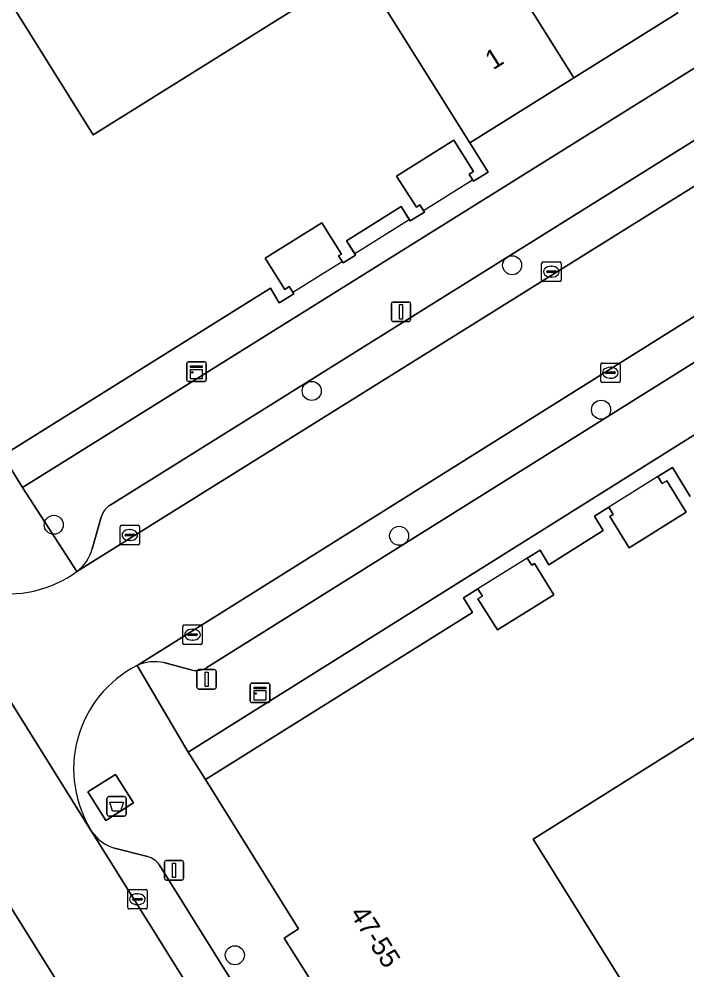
# Model space of a CAD drawing. Extents: x 159664 to 160323, y 385312 to 386115.
# Drawn here: x 159990.16 to 160024.46, y 385782.67 to 385831.48 of the extents above; entities that cross this region are included whole.
import ezdxf

# ---------------------------------------------------------------- set-up
doc = ezdxf.new("R2010")
doc.units = 0
for name, color, linetype in [('IMGEO_Afval_apart_plaats', 7, 'Continuous'), ('IMGEO_Boom', 7, 'Continuous'), ('IMGEO_Erf', 7, 'Continuous'), ('IMGEO_Kast', 7, 'Continuous'), ('IMGEO_Kolk', 7, 'Continuous'), ('IMGEO_Lichtmast', 7, 'Continuous'), ('IMGEO_Pand', 7, 'Continuous'), ('IMGEO_Pand_nummerreeks', 7, 'Continuous'), ('IMGEO_Pand_overbouw', 7, 'Continuous'), ('IMGEO_Parkeervlak_open', 7, 'Continuous'), ('IMGEO_Rijbaan_lokaal_open', 7, 'Continuous'), ('IMGEO_Voetpad_gesloten', 7, 'Continuous'), ('IMGEO_Voetpad_open', 7, 'Continuous')]:
    doc.layers.add(name, color=color, linetype=linetype)

msp = doc.modelspace()

# ---------------------------------------------------------------- linework, layer by layer
at = {"layer": 'IMGEO_Afval_apart_plaats'}
for p, q in [((159994.675, 385790.674), (159994.675, 385791.474)), ((159994.675, 385791.474), (159994.675, 385790.674)), ((159994.775, 385791.574), (159995.565, 385791.574)), ((159995.565, 385791.574), (159994.775, 385791.574)), ((159995.665, 385791.474), (159995.665, 385790.674)), ((159995.665, 385790.674), (159995.665, 385791.474)), ((159995.565, 385790.574), (159994.775, 385790.574)), ((159994.775, 385790.574), (159995.565, 385790.574))]:
    msp.add_line(p, q, dxfattribs=at)
msp.add_lwpolyline([(159994.818, 385791.288), (159995.522, 385791.288), (159995.373, 385790.818), (159994.967, 385790.818), (159994.818, 385791.288)], dxfattribs=at)
for centre, start, end in [((159994.775, 385791.474), 90, 180), ((159994.775, 385791.474), 90, 180), ((159995.565, 385791.474), 0, 90), ((159995.565, 385791.474), 360, 90), ((159994.775, 385790.674), 180, 270), ((159994.775, 385790.674), 180, 270), ((159995.565, 385790.674), 270, 0), ((159995.565, 385790.674), 270, 0)]:
    msp.add_arc(centre, 0.1, start, end, dxfattribs=at)
at = {"layer": 'IMGEO_Boom'}
for centre in [(160015.483, 385818.84), (160005.192, 385812.388), (160020.052, 385811.427), (159991.944, 385805.52), (160009.679, 385804.956), (160001.243, 385783.428)]:
    msp.add_circle(centre, 0.489, dxfattribs=at)
at = {"layer": 'IMGEO_Erf'}
for points in [[(159986.779, 385837.03), (159993.962, 385825.534), (160007.687, 385834.102)], [(160023.99, 385831.793), (160018.647, 385828.455), (160013.305, 385825.116), (160014.244, 385823.616), (160013.502, 385823.151), (160013.274, 385823.516), (160013.494, 385823.654), (160012.491, 385825.256), (160009.552, 385823.409), (160010.574, 385821.819), (160010.751, 385821.933), (160010.983, 385821.572), (160010.245, 385821.112), (160009.785, 385821.85), (160006.978, 385820.1), (160007.447, 385819.366), (160006.799, 385818.956), (160006.571, 385819.321), (160006.715, 385819.411), (160005.715, 385821.015), (160002.808, 385819.202), (160003.803, 385817.596), (160004.041, 385817.743), (160004.267, 385817.378), (160003.524, 385816.917), (160003.066, 385817.656), (159989.327, 385809.076), (159990.336, 385807.428), (160038.523, 385837.501)], [(160047.785, 385824.505), (159998.838, 385793.855), (159999.73, 385792.444), (160013.448, 385801.025), (160012.988, 385801.763), (160013.729, 385802.225), (160013.956, 385801.861), (160013.727, 385801.718), (160014.723, 385800.123), (160017.631, 385801.928), (160016.64, 385803.538), (160016.487, 385803.443), (160016.261, 385803.81), (160016.917, 385804.213), (160017.373, 385803.472), (160020.164, 385805.223), (160019.705, 385805.962), (160020.443, 385806.42), (160020.669, 385806.054), (160020.498, 385805.949), (160021.488, 385804.339), (160024.423, 385806.167), (160023.434, 385807.777), (160023.195, 385807.631), (160022.97, 385807.997), (160023.715, 385808.455), (160024.631, 385806.964)], [(160045.382, 385808.721), (160040.222, 385805.5), (160041.856, 385802.883), (160036.512, 385799.546), (160034.877, 385802.164), (160029.715, 385798.943), (160029.532, 385798.829), (160030.123, 385797.883), (160016.558, 385789.392), (160023.715, 385777.928)]]:
    msp.add_lwpolyline(points, dxfattribs=at)
at = {"layer": 'IMGEO_Kast'}
for p, q in [((159998.777, 385812.955), (159998.777, 385813.796)), ((159998.777, 385813.796), (159998.777, 385812.955)), ((159998.852, 385813.88), (159999.693, 385813.88)), ((159999.693, 385813.88), (159998.852, 385813.88)), ((159999.777, 385813.805), (159999.777, 385812.964)), ((159999.777, 385812.964), (159999.777, 385813.805)), ((159999.702, 385812.88), (159998.861, 385812.88)), ((159998.861, 385812.88), (159999.702, 385812.88)), ((160002.037, 385796.472), (160002.037, 385797.313)), ((160002.037, 385797.313), (160002.037, 385796.472)), ((160002.112, 385797.397), (160002.953, 385797.397)), ((160002.953, 385797.397), (160002.112, 385797.397)), ((160003.037, 385797.322), (160003.037, 385796.481)), ((160003.037, 385796.481), (160003.037, 385797.322)), ((160002.962, 385796.397), (160002.121, 385796.397)), ((160002.121, 385796.397), (160002.962, 385796.397))]:
    msp.add_line(p, q, dxfattribs=at)
for points in [[(159998.972, 385813.67), (159999.572, 385813.67), (159999.572, 385813.585), (159998.972, 385813.585), (159998.972, 385813.67)], [(159998.972, 385813.495), (159999.572, 385813.495), (159999.572, 385813.006), (159998.972, 385813.006), (159998.972, 385813.495)], [(160002.232, 385797.187), (160002.832, 385797.187), (160002.832, 385797.102), (160002.232, 385797.102), (160002.232, 385797.187)], [(160002.232, 385797.012), (160002.832, 385797.012), (160002.832, 385796.523), (160002.232, 385796.523), (160002.232, 385797.012)]]:
    msp.add_lwpolyline(points, dxfattribs=at)
for centre in [(159999.056, 385813.344), (160002.316, 385796.861)]:
    msp.add_circle(centre, 0.0377, dxfattribs=at)
for centre, start, end in [((159998.855, 385813.802), 92.4484, 184.2845), ((159998.855, 385813.802), 92.4484, 184.2845), ((159999.699, 385813.802), 2.4484, 94.2845), ((159999.699, 385813.802), 2.4484, 94.2845), ((159998.855, 385812.958), 182.4484, 274.2845), ((159998.855, 385812.958), 182.4484, 274.2845), ((159999.699, 385812.958), 272.4484, 4.2845), ((159999.699, 385812.958), 272.4484, 4.2845), ((160002.115, 385797.319), 92.4484, 184.2845), ((160002.115, 385797.319), 92.4484, 184.2845), ((160002.959, 385797.319), 2.4484, 94.2845), ((160002.959, 385797.319), 2.4484, 94.2845), ((160002.115, 385796.475), 182.4484, 274.2845), ((160002.115, 385796.475), 182.4484, 274.2845), ((160002.959, 385796.475), 272.4484, 4.2845), ((160002.959, 385796.475), 272.4484, 4.2845)]:
    msp.add_arc(centre, 0.0779, start, end, dxfattribs=at)
at = {"layer": 'IMGEO_Kolk'}
for p, q in [((160017.073, 385819.009), (160017.925, 385819.009)), ((160016.998, 385818.083), (160016.998, 385818.935)), ((160017.257, 385818.503), (160017.257, 385818.515)), ((160017.3, 385818.552), (160017.698, 385818.552)), ((160017.486, 385818.789), (160017.511, 385818.789)), ((160017.741, 385818.515), (160017.741, 385818.503)), ((160017.999, 385818.935), (160017.999, 385818.083)), ((160017.925, 385818.009), (160017.073, 385818.009)), ((160017.695, 385818.466), (160017.297, 385818.466)), ((160017.509, 385818.229), (160017.484, 385818.229)), ((160020.03, 385812.897), (160020.03, 385813.749)), ((160020.105, 385813.823), (160020.957, 385813.823)), ((160020.518, 385813.603), (160020.543, 385813.603)), ((160021.031, 385813.749), (160021.031, 385812.897)), ((160020.289, 385813.317), (160020.289, 385813.329)), ((160020.727, 385813.28), (160020.329, 385813.28)), ((160020.332, 385813.366), (160020.73, 385813.366)), ((160020.773, 385813.329), (160020.773, 385813.317)), ((160020.957, 385812.823), (160020.105, 385812.823)), ((160020.541, 385813.043), (160020.516, 385813.043)), ((159995.35, 385804.567), (159995.35, 385805.419)), ((159995.425, 385805.493), (159996.277, 385805.493)), ((159996.351, 385805.419), (159996.351, 385804.567)), ((159995.609, 385804.987), (159995.609, 385804.999)), ((159996.047, 385804.95), (159995.649, 385804.95)), ((159995.652, 385805.036), (159996.05, 385805.036)), ((159995.838, 385805.273), (159995.863, 385805.273)), ((159996.093, 385804.999), (159996.093, 385804.987)), ((159996.277, 385804.493), (159995.425, 385804.493)), ((159995.861, 385804.713), (159995.836, 385804.713)), ((159998.57, 385799.452), (159998.57, 385800.304)), ((159998.645, 385800.378), (159999.497, 385800.378)), ((159999.058, 385800.158), (159999.083, 385800.158)), ((159999.571, 385800.304), (159999.571, 385799.452)), ((159998.829, 385799.872), (159998.829, 385799.884)), ((159999.267, 385799.835), (159998.869, 385799.835)), ((159998.872, 385799.921), (159999.27, 385799.921)), ((159999.081, 385799.598), (159999.056, 385799.598)), ((159999.313, 385799.884), (159999.313, 385799.872)), ((159999.497, 385799.378), (159998.645, 385799.378)), ((159995.816, 385786.802), (159996.668, 385786.802)), ((159995.741, 385785.876), (159995.741, 385786.728)), ((159996, 385786.296), (159996, 385786.308)), ((159996.043, 385786.345), (159996.441, 385786.345)), ((159996.229, 385786.582), (159996.254, 385786.582)), ((159996.484, 385786.308), (159996.484, 385786.296)), ((159996.742, 385786.728), (159996.742, 385785.876)), ((159996.668, 385785.802), (159995.816, 385785.802)), ((159996.438, 385786.259), (159996.04, 385786.259)), ((159996.252, 385786.022), (159996.227, 385786.022))]:
    msp.add_line(p, q, dxfattribs=at)
for points in [[(160017.073, 385819.009), (160017.925, 385819.009)], [(160016.998, 385818.083), (160016.998, 385818.935)], [(160017.999, 385818.935), (160017.999, 385818.083)], [(160017.925, 385818.009), (160017.073, 385818.009)], [(160020.03, 385812.897), (160020.03, 385813.749)], [(160020.105, 385813.823), (160020.957, 385813.823)], [(160021.031, 385813.749), (160021.031, 385812.897)], [(160020.957, 385812.823), (160020.105, 385812.823)], [(159995.35, 385804.567), (159995.35, 385805.419)], [(159995.425, 385805.493), (159996.277, 385805.493)], [(159996.351, 385805.419), (159996.351, 385804.567)], [(159996.277, 385804.493), (159995.425, 385804.493)], [(159998.57, 385799.452), (159998.57, 385800.304)], [(159998.645, 385800.378), (159999.497, 385800.378)], [(159999.571, 385800.304), (159999.571, 385799.452)], [(159999.497, 385799.378), (159998.645, 385799.378)], [(159995.816, 385786.802), (159996.668, 385786.802)], [(159995.741, 385785.876), (159995.741, 385786.728)], [(159996.742, 385786.728), (159996.742, 385785.876)], [(159996.668, 385785.802), (159995.816, 385785.802)]]:
    msp.add_lwpolyline(points, dxfattribs=at)
for centre, radius, start, end in [((160017.075, 385818.933), 0.0765, 91.552, 178.448), ((160017.075, 385818.933), 0.0765, 91.552, 178.448), ((160017.923, 385818.933), 0.0765, 1.552, 88.448), ((160017.923, 385818.933), 0.0765, 1.552, 88.448), ((160017.297, 385818.512), 0.0403, 85.8775, 175.7526), ((160017.294, 385818.502), 0.0366, 178.938, 274.7102), ((160017.698, 385818.509), 0.043, 264.8664, 352.4533), ((160017.702, 385818.514), 0.0386, 1.7309, 96.639), ((160017.075, 385818.085), 0.0765, 181.552, 268.448), ((160017.075, 385818.085), 0.0765, 181.552, 268.448), ((160017.923, 385818.085), 0.0765, 271.552, 358.448), ((160017.923, 385818.085), 0.0765, 271.552, 358.448), ((160020.107, 385813.747), 0.0765, 91.552, 178.448), ((160020.107, 385813.747), 0.0765, 91.552, 178.448), ((160020.955, 385813.747), 0.0765, 1.552, 88.448), ((160020.955, 385813.747), 0.0765, 1.552, 88.448), ((160020.329, 385813.326), 0.0403, 85.8775, 175.7526), ((160020.326, 385813.316), 0.0366, 178.938, 274.7102), ((160020.73, 385813.323), 0.043, 264.8664, 352.4533), ((160020.734, 385813.328), 0.0386, 1.7309, 96.639), ((160020.107, 385812.899), 0.0765, 181.552, 268.448), ((160020.107, 385812.899), 0.0765, 181.552, 268.448), ((160020.955, 385812.899), 0.0765, 271.552, 358.448), ((160020.955, 385812.899), 0.0765, 271.552, 358.448), ((159995.427, 385805.417), 0.0765, 91.552, 178.448), ((159995.427, 385805.417), 0.0765, 91.552, 178.448), ((159996.275, 385805.417), 0.0765, 1.552, 88.448), ((159996.275, 385805.417), 0.0765, 1.552, 88.448), ((159995.649, 385804.996), 0.0403, 85.8775, 175.7526), ((159995.646, 385804.986), 0.0366, 178.938, 274.7102), ((159996.05, 385804.993), 0.043, 264.8664, 352.4533), ((159996.054, 385804.998), 0.0386, 1.7309, 96.639), ((159995.427, 385804.569), 0.0765, 181.552, 268.448), ((159995.427, 385804.569), 0.0765, 181.552, 268.448), ((159996.275, 385804.569), 0.0765, 271.552, 358.448), ((159996.275, 385804.569), 0.0765, 271.552, 358.448), ((159998.647, 385800.302), 0.0765, 91.552, 178.448), ((159998.647, 385800.302), 0.0765, 91.552, 178.448), ((159999.495, 385800.302), 0.0765, 1.552, 88.448), ((159999.495, 385800.302), 0.0765, 1.552, 88.448), ((159998.647, 385799.454), 0.0765, 181.552, 268.448), ((159998.647, 385799.454), 0.0765, 181.552, 268.448), ((159998.869, 385799.881), 0.0403, 85.8775, 175.7526), ((159998.866, 385799.871), 0.0366, 178.938, 274.7102), ((159999.27, 385799.878), 0.043, 264.8664, 352.4533), ((159999.274, 385799.883), 0.0386, 1.7309, 96.639), ((159999.495, 385799.454), 0.0765, 271.552, 358.448), ((159999.495, 385799.454), 0.0765, 271.552, 358.448), ((159995.818, 385786.726), 0.0765, 91.552, 178.448), ((159995.818, 385786.726), 0.0765, 91.552, 178.448), ((159996.666, 385786.726), 0.0765, 1.552, 88.448), ((159996.666, 385786.726), 0.0765, 1.552, 88.448), ((159996.04, 385786.305), 0.0403, 85.8775, 175.7526), ((159996.037, 385786.295), 0.0366, 178.938, 274.7102), ((159996.441, 385786.302), 0.043, 264.8664, 352.4533), ((159996.445, 385786.307), 0.0386, 1.7309, 96.639), ((159995.818, 385785.878), 0.0765, 181.552, 268.448), ((159995.818, 385785.878), 0.0765, 181.552, 268.448), ((159996.666, 385785.878), 0.0765, 271.552, 358.448), ((159996.666, 385785.878), 0.0765, 271.552, 358.448)]:
    msp.add_arc(centre, radius, start, end, dxfattribs=at)
for centre, major_axis, ratio, start_param, end_param in [((160017.485, 385818.509), (-0.387, 0.002), 0.722429, 4.712389, 7.853982), ((160017.51, 385818.509), (-0.39, 0.002), 0.717154, 1.570796, 4.712389), ((160020.517, 385813.323), (-0.387, 0.002), 0.722429, 4.712389, 7.853982), ((160020.542, 385813.323), (-0.39, 0.002), 0.717154, 1.570796, 4.712389), ((159995.837, 385804.993), (-0.387, 0.002), 0.722429, 4.712389, 7.853982), ((159995.862, 385804.993), (-0.39, 0.002), 0.717154, 1.570796, 4.712389), ((159999.057, 385799.878), (-0.387, 0.002), 0.722429, 4.712389, 7.853982), ((159999.082, 385799.878), (-0.39, 0.002), 0.717154, 1.570796, 4.712389), ((159996.228, 385786.302), (-0.387, 0.002), 0.722429, 4.712389, 7.853982), ((159996.253, 385786.302), (-0.39, 0.002), 0.717154, 1.570796, 4.712389)]:
    msp.add_ellipse(centre, major_axis=major_axis, ratio=ratio, start_param=start_param, end_param=end_param, dxfattribs=at)
at = {"layer": 'IMGEO_Lichtmast'}
for p, q in [((160009.281, 385816.052), (160009.281, 385816.852)), ((160009.281, 385816.852), (160009.281, 385816.052)), ((160009.381, 385816.952), (160010.171, 385816.952)), ((160010.171, 385816.952), (160009.381, 385816.952)), ((160010.271, 385816.852), (160010.271, 385816.052)), ((160010.271, 385816.052), (160010.271, 385816.852)), ((160010.171, 385815.952), (160009.381, 385815.952)), ((160009.381, 385815.952), (160010.171, 385815.952)), ((159999.297, 385797.189), (159999.297, 385797.989)), ((159999.297, 385797.989), (159999.297, 385797.189)), ((159999.397, 385798.089), (160000.187, 385798.089)), ((160000.187, 385798.089), (159999.397, 385798.089)), ((160000.287, 385797.989), (160000.287, 385797.189)), ((160000.287, 385797.189), (160000.287, 385797.989)), ((160000.187, 385797.089), (159999.397, 385797.089)), ((159999.397, 385797.089), (160000.187, 385797.089)), ((159997.725, 385788.286), (159998.515, 385788.286)), ((159998.515, 385788.286), (159997.725, 385788.286)), ((159997.625, 385787.386), (159997.625, 385788.186)), ((159997.625, 385788.186), (159997.625, 385787.386)), ((159998.615, 385788.186), (159998.615, 385787.386)), ((159998.615, 385787.386), (159998.615, 385788.186)), ((159998.515, 385787.286), (159997.725, 385787.286)), ((159997.725, 385787.286), (159998.515, 385787.286))]:
    msp.add_line(p, q, dxfattribs=at)
for points in [[(160009.701, 385816.827), (160009.851, 385816.827), (160009.851, 385816.077), (160009.701, 385816.077), (160009.701, 385816.827)], [(159999.717, 385797.964), (159999.867, 385797.964), (159999.867, 385797.214), (159999.717, 385797.214), (159999.717, 385797.964)], [(159998.045, 385788.161), (159998.195, 385788.161), (159998.195, 385787.411), (159998.045, 385787.411), (159998.045, 385788.161)]]:
    msp.add_lwpolyline(points, dxfattribs=at)
for centre, start, end in [((160009.381, 385816.852), 90, 180), ((160009.381, 385816.852), 90, 180), ((160010.171, 385816.852), 0, 90), ((160010.171, 385816.852), 360, 90), ((160009.381, 385816.052), 180, 270), ((160009.381, 385816.052), 180, 270), ((160010.171, 385816.052), 270, 0), ((160010.171, 385816.052), 270, 0), ((159999.397, 385797.989), 90, 180), ((159999.397, 385797.989), 90, 180), ((160000.187, 385797.989), 0, 90), ((160000.187, 385797.989), 360, 90), ((159999.397, 385797.189), 180, 270), ((159999.397, 385797.189), 180, 270), ((160000.187, 385797.189), 270, 0), ((160000.187, 385797.189), 270, 0), ((159997.725, 385788.186), 90, 180), ((159997.725, 385788.186), 90, 180), ((159998.515, 385788.186), 0, 90), ((159998.515, 385788.186), 360, 90), ((159997.725, 385787.386), 180, 270), ((159997.725, 385787.386), 180, 270), ((159998.515, 385787.386), 270, 0), ((159998.515, 385787.386), 270, 0)]:
    msp.add_arc(centre, 0.1, start, end, dxfattribs=at)
at = {"layer": 'IMGEO_Pand'}
for points in [[(160018.647, 385828.455), (160023.99, 385831.793), (160018.95, 385839.855), (160013.606, 385836.519)], [(160013.305, 385825.116), (160018.647, 385828.455), (160013.606, 385836.519), (160008.262, 385833.182)]]:
    msp.add_lwpolyline(points, close=True, dxfattribs=at)
for points in [[(160007.687, 385834.102), (159993.962, 385825.534), (159986.779, 385837.03)], [(159989.327, 385809.076), (160003.066, 385817.656), (160003.524, 385816.917), (160004.267, 385817.378), (160004.041, 385817.743), (160003.803, 385817.596), (160002.808, 385819.202), (160005.715, 385821.015), (160006.715, 385819.411), (160006.571, 385819.321), (160006.799, 385818.956), (160007.447, 385819.366), (160006.978, 385820.1), (160009.785, 385821.85), (160010.245, 385821.112), (160010.983, 385821.572), (160010.751, 385821.933), (160010.574, 385821.819), (160009.552, 385823.409), (160012.491, 385825.256), (160013.494, 385823.654), (160013.274, 385823.516), (160013.502, 385823.151), (160014.244, 385823.616), (160013.305, 385825.116), (160008.262, 385833.182)], [(160024.631, 385806.964), (160023.715, 385808.455), (160022.97, 385807.997), (160023.195, 385807.631), (160023.434, 385807.777), (160024.423, 385806.167), (160021.488, 385804.339), (160020.498, 385805.949), (160020.669, 385806.054), (160020.443, 385806.42), (160019.705, 385805.962), (160020.164, 385805.223), (160017.373, 385803.472), (160016.917, 385804.213), (160016.261, 385803.81), (160016.487, 385803.443), (160016.64, 385803.538), (160017.631, 385801.928), (160014.723, 385800.123), (160013.727, 385801.718), (160013.956, 385801.861), (160013.729, 385802.225), (160012.988, 385801.763), (160013.448, 385801.025), (159999.73, 385792.444), (160004.52, 385784.778), (160003.776, 385784.309), (160006.266, 385780.362)], [(160023.715, 385777.928), (160016.558, 385789.392), (160030.123, 385797.883)]]:
    msp.add_lwpolyline(points, dxfattribs=at)
at = {"layer": 'IMGEO_Pand_overbouw'}
for points in [[(160010.933, 385821.65), (160013.455, 385823.226), (160013.274, 385823.516), (160013.494, 385823.654), (160012.491, 385825.256), (160009.552, 385823.409), (160010.574, 385821.819), (160010.751, 385821.933)], [(160007.399, 385819.441), (160010.197, 385821.19), (160009.785, 385821.85), (160006.978, 385820.1)], [(160004.22, 385817.454), (160006.749, 385819.035), (160006.571, 385819.321), (160006.715, 385819.411), (160005.715, 385821.015), (160002.808, 385819.202), (160003.803, 385817.596), (160004.041, 385817.743)], [(160023.434, 385807.777), (160023.195, 385807.631), (160022.97, 385807.997), (160020.443, 385806.42), (160020.669, 385806.054), (160020.498, 385805.949), (160021.488, 385804.339), (160024.423, 385806.167)], [(160016.64, 385803.538), (160016.487, 385803.443), (160016.261, 385803.81), (160013.729, 385802.225), (160013.956, 385801.861), (160013.727, 385801.718), (160014.723, 385800.123), (160017.631, 385801.928)]]:
    msp.add_lwpolyline(points, close=True, dxfattribs=at)
at = {"layer": 'IMGEO_Parkeervlak_open'}
for points in [[(159993.137, 385803.124), (160037.646, 385830.886)], [(160033.911, 385830.905), (159994.835, 385806.533)], [(160040.643, 385826.109), (159996.221, 385798.296)], [(159999.803, 385798.19), (160038.885, 385822.649)], [(159996.446, 385775.16), (159973.561, 385811.75)], [(159994.384, 385805.91), (159993.916, 385804.287)], [(159997.603, 385798.448), (159999.057, 385798.06)], [(159993.907, 385789.767), (160001.195, 385778.092)], [(159996.754, 385788.5), (159995.056, 385788.931)], [(160049.599, 385704.422), (159997.375, 385788.05)]]:
    msp.add_lwpolyline(points, dxfattribs=at)
for centre, radius, start, end in [((159995.399, 385805.65), 1.048, 122.5674, 165.6298), ((159991.727, 385804.911), 2.277, 308.2817, 344.0884), ((159997.143, 385796.276), 2.22, 78.0284, 114.5245), ((159999.263, 385799.084), 1.045, 258.6373, 301.1332), ((159995.599, 385790.885), 2.028, 213.4544, 254.4671), ((159996.461, 385787.442), 1.098, 33.6378, 74.5052)]:
    msp.add_arc(centre, radius, start, end, dxfattribs=at)
at = {"layer": 'IMGEO_Rijbaan_lokaal_open'}
for points in [[(160040.643, 385826.109), (160037.646, 385830.886), (159993.137, 385803.124)], [(159996.221, 385798.296), (160040.643, 385826.109)], [(159984.548, 385804.758), (159984.575, 385804.705), (159993.83, 385789.869), (159993.907, 385789.767)]]:
    msp.add_lwpolyline(points, dxfattribs=at)
msp.add_lwpolyline([(159984.548, 385804.758), (159984.204, 385805.319), (159978.328, 385814.729), (159973.561, 385811.75), (159996.446, 385775.16), (160001.195, 385778.092), (159993.907, 385789.767), (159993.83, 385789.869), (159984.575, 385804.705)], close=True, dxfattribs=at)
for centre, radius, start, end in [((159989.606, 385807.956), 5.985, 212.3032, 306.154), ((159998.93, 385792.983), 5.964, 117.0168, 212.6242)]:
    msp.add_arc(centre, radius, start, end, dxfattribs=at)
at = {"layer": 'IMGEO_Voetpad_gesloten'}
msp.add_lwpolyline([(159995.113, 385792.711), (159993.698, 385791.815), (159994.625, 385790.351), (159996.04, 385791.247)], close=True, dxfattribs=at)
at = {"layer": 'IMGEO_Voetpad_open'}
for points in [[(160040.915, 385833.676), (160038.523, 385837.501), (159990.336, 385807.428), (159993.137, 385803.124)], [(159994.835, 385806.533), (160033.911, 385830.905)], [(159996.221, 385798.296), (159998.838, 385793.855), (160047.785, 385824.505)], [(160038.885, 385822.649), (159999.803, 385798.19)], [(159993.137, 385803.124), (159990.336, 385807.428), (159989.327, 385809.076), (159984.547, 385816.744)], [(159993.916, 385804.287), (159994.384, 385805.91)], [(160078.734, 385663.796), (160078.117, 385664.783), (160054.519, 385702.551), (160052.447, 385705.856), (160028.847, 385743.663), (160028.058, 385744.928), (160014.563, 385766.547), (160015.754, 385767.302), (160015.345, 385767.95), (160013.573, 385770.795), (160013.229, 385771.341), (160013.974, 385771.81), (160007.966, 385781.427), (160006.266, 385780.362), (160003.776, 385784.309), (160004.52, 385784.778), (159999.73, 385792.444), (159998.838, 385793.855), (159996.221, 385798.296)], [(159999.057, 385798.06), (159997.603, 385798.448)], [(159995.056, 385788.931), (159996.754, 385788.5)], [(159997.375, 385788.05), (160049.599, 385704.422), (160049.977, 385704.655), (160052.374, 385700.847), (160052.004, 385700.609), (160087.506, 385643.762)]]:
    msp.add_lwpolyline(points, dxfattribs=at)
msp.add_lwpolyline([(159994.625, 385790.351), (159993.698, 385791.815), (159995.113, 385792.711), (159996.04, 385791.247)], close=True, dxfattribs=at)
for centre, radius, start, end in [((159995.399, 385805.65), 1.048, 122.5674, 165.6298), ((159989.606, 385807.956), 5.985, 212.3032, 306.154), ((159991.727, 385804.911), 2.277, 308.2817, 344.0884), ((159997.143, 385796.276), 2.22, 78.0284, 114.5245), ((159998.93, 385792.983), 5.964, 117.0168, 212.6242), ((159999.263, 385799.084), 1.045, 258.6373, 301.1332), ((159995.599, 385790.885), 2.028, 213.4544, 254.4671), ((159996.461, 385787.442), 1.098, 33.6378, 74.5052)]:
    msp.add_arc(centre, radius, start, end, dxfattribs=at)

# ---------------------------------------------------------------- texts
at = {"layer": 'IMGEO_Pand_nummerreeks'}
for s, rotation, p in [('1', 32.0003, (160014.504, 385828.837)), ('47-55', 302.6068, (160007.122, 385785.563))]:
    msp.add_text(s, height=1, rotation=rotation, dxfattribs=at).set_placement(p)

doc.saveas('drawing.dxf')
